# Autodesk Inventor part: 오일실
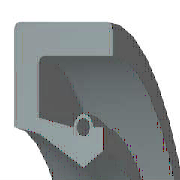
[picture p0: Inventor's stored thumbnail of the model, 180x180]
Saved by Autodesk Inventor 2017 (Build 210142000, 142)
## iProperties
IsCustomPart: 0
Created: 2009-02
Part Number: 오일실
Material: 고무
Description: 오일-실
Document SubType Name: Modeling
Standard: KS B 2804
Standards Organization: KS
Language: ko-KR
Size Designation: S - 17 30 8
Categories: <MemberInstance><Categories><Category DisplayName="샤프트 부품" InternalName="7f7aeb1f-a693-4053-b835-cee3144e0d98" Mnemonic="SHFT"><Category DisplayName="실링" Intern
Density: 0.93 g/cm^3
Appearance: 고무 - 검은색 - 버전 1.1
Author: pww
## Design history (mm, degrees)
revolve "본체" stored, may be unused: angle "d17" = 90 deg
revolve "스프링1" stored, may be unused: angle "d18" = 90 deg
body "Solid1"
sketch "스케치1"
  geometry: L1 (0, 15)-(8, 15); L2 (8, 15)-(8, 13.75); L3 (8, 13.75)-(1.75, 13.75); L4 (0, 15)-(0, 10.6); L5 (0, 10.6)-(1.75, 10.25); L6 (1.75, 10.25)-(4.9, 8.5); L7 (4.9, 8.5)-(0, 8.5); L8 (6.3, 9.375)-(6.3, 10.6); L9 (0, 0)-(9.586, 0) reference; L10 (4.9, 8.5)-(6.3, 9.375); L11 (0, 18)-(0, -3) reference; L12 (-1.917, 0)-(11.503, 0) reference; L13 (4.2, 10.6)-(1.75, 11.09); L14 (1.75, 11.09)-(1.75, 13.75); L15 (6.3, 10.6)-(5.6, 10.6); C1 r 0.455 at (4.9, 10.6); A1 r 0.7 centre (4.9, 10.6) between (5.6, 10.6) and (4.2, 10.6)
  constraints: 26 end point, 5 horizontal alignment, 4 perpendicular, 2 centre point, 2 collinear, 2 horizontal, 2 parallel, 2 point on circle, 2 point on line, 2 vertical alignment, 1 coincident
  dimensions: "d0" = 30 diameter of L1 L9 (= SD2); "d1" = 18.75 diameter of L8.start L9 (= ABDM); "d2" = 1.25 distance of L1.end L2.end (computed from SD); "d3" = 0.91 diameter of C1 (= SPDI); "d4" = 1.4 diameter of A1 (= SPDA); "d5" = 17 diameter of L6.end L9 (= NND); "d6" = 20.5 diameter of L5.end L9 (= TKDM); "d7" = 21.2 diameter of L4.end L9 (= HLDM); "d8" = 4.9 distance from line of C1.centre L4 (= SPDST); "d9" = 6.3 distance between parallel lines of L8 L4 (= SDI); "d10" = 8 distance between parallel lines of L2 L4 (= SWDT); "d12" = 1.75 distance between parallel lines of L14 L4 (= SD)
fillet "모깎기1" dims "d11" = 0.3 (= RR)
other parameters: "SD2" = 30 [user parameter; used in 1 equation term], "SWDT" = 8 [user parameter; used in 1 equation term], "RR" = 0.3 [user parameter; used in 1 equation term], "SD" = 1.75 [user parameter; used in 2 equation terms], "NND" = 17 [user parameter; used in 1 equation term], "SPDA" = 1.4 [user parameter; used in 1 equation term], "SPDI" = 0.91 [user parameter; used in 1 equation term], "TKDM" = 20.5 [user parameter; used in 1 equation term], "HLDM" = 21.2 [user parameter; used in 1 equation term], "ABDM" = 18.75 [user parameter; used in 1 equation term], "SDI" = 6.3 [user parameter; used in 1 equation term], "SPDST" = 4.9 [user parameter; used in 1 equation term], "d13" = 0, "d14" = 0, "d15" = 0, "LAB" = 0.35 [user parameter]
